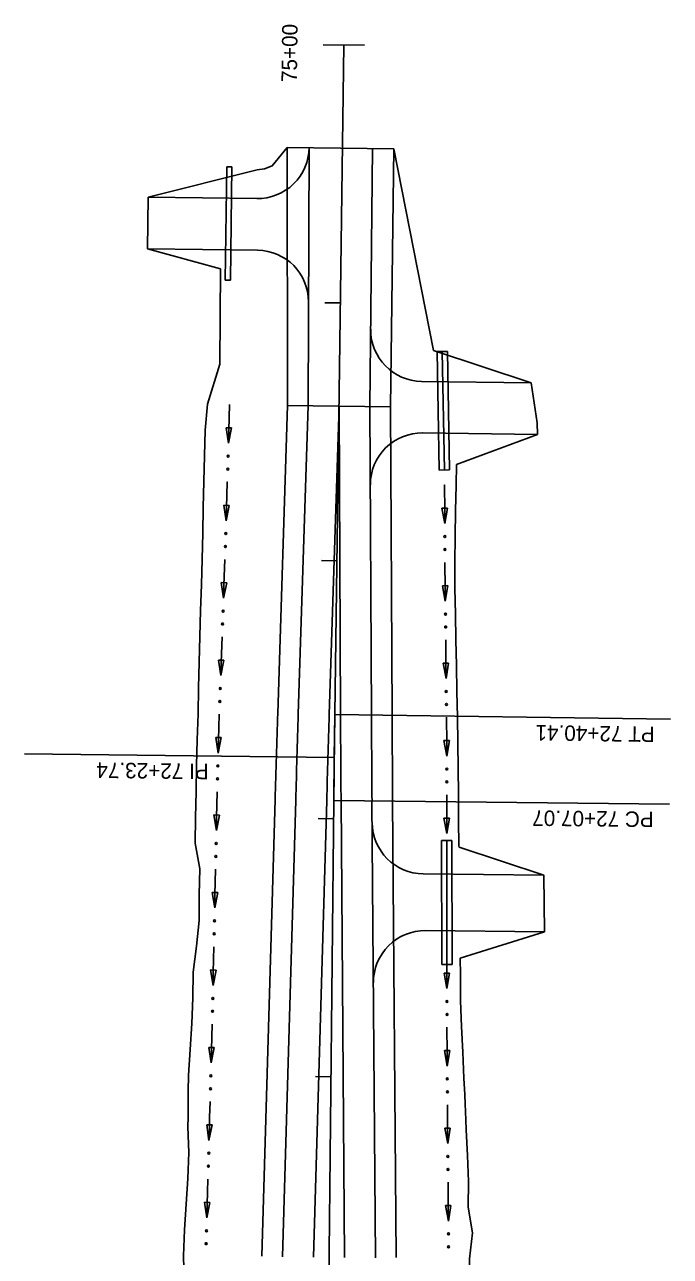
# Model space of a CAD drawing. Extents: x 1611108 to 1749517, y 619561 to 797725.
# Drawn here: x 1728212.3 to 1728462.5, y 773287.1 to 773764.5 of the extents above; entities that cross this region are included whole.
import ezdxf

# ---------------------------------------------------------------- set-up
doc = ezdxf.new("R2010")
doc.units = 0
for name, color, linetype in [('R_Ditch', 7, 'Continuous'), ('R_Drainage', 7, 'Continuous'), ('R_Horz Alg', 7, 'Continuous'), ('R_Horz Alg Annot', 7, 'Continuous'), ('R_Horz Alg Annot_Side Road', 7, 'Continuous'), ('R_Horz Alg Stationing_Side Road', 7, 'Continuous'), ('R_Proposed Const Limits', 7, 'Continuous'), ('R_Proposed Road', 7, 'Continuous'), ('R_Striping', 7, 'Continuous')]:
    doc.layers.add(name, color=color, linetype=linetype)

msp = doc.modelspace()

# ---------------------------------------------------------------- linework, layer by layer
at = {"layer": 'R_Ditch'}
for p, q in [((1728292.54, 773608.22), (1728290.42, 773608.28)), ((1728290.42, 773608.28), (1728291.3, 773602.25)), ((1728291.3, 773602.25), (1728292.54, 773608.22)), ((1728291.62, 773578.2), (1728289.5, 773578.26)), ((1728289.5, 773578.26), (1728290.38, 773572.23)), ((1728290.38, 773572.23), (1728291.62, 773578.2)), ((1728376.17, 773577.1), (1728374.05, 773577.09)), ((1728374.05, 773577.09), (1728375.13, 773571.1)), ((1728375.13, 773571.1), (1728376.17, 773577.1)), ((1728290.65, 773548.17), (1728288.53, 773548.24)), ((1728288.53, 773548.24), (1728289.38, 773542.21)), ((1728289.38, 773542.21), (1728290.65, 773548.17)), ((1728376.34, 773547.07), (1728374.23, 773547.05)), ((1728374.23, 773547.05), (1728375.34, 773541.06)), ((1728375.34, 773541.06), (1728376.34, 773547.07)), ((1728289.57, 773518.15), (1728287.45, 773518.22)), ((1728287.45, 773518.22), (1728288.3, 773512.19)), ((1728288.3, 773512.19), (1728289.57, 773518.15)), ((1728376.63, 773517.03), (1728374.51, 773517.01)), ((1728374.51, 773517.01), (1728375.63, 773511.02)), ((1728375.63, 773511.02), (1728376.63, 773517.03)), ((1728288.48, 773488.14), (1728286.37, 773488.19)), ((1728286.37, 773488.19), (1728287.29, 773482.17)), ((1728287.29, 773482.17), (1728288.48, 773488.14)), ((1728376.93, 773486.99), (1728374.81, 773486.99)), ((1728374.81, 773486.99), (1728375.87, 773480.99)), ((1728375.87, 773480.99), (1728376.93, 773486.99)), ((1728287.81, 773458.11), (1728285.7, 773458.16)), ((1728285.7, 773458.16), (1728286.62, 773452.14)), ((1728286.62, 773452.14), (1728287.81, 773458.11)), ((1728376.94, 773456.95), (1728374.82, 773456.95)), ((1728374.82, 773456.95), (1728375.88, 773450.95)), ((1728375.88, 773450.95), (1728376.94, 773456.95)), ((1728287.16, 773428.08), (1728285.05, 773428.13)), ((1728285.05, 773428.13), (1728285.98, 773422.11)), ((1728285.98, 773422.11), (1728287.16, 773428.08)), ((1728286.52, 773398.05), (1728284.4, 773398.1)), ((1728284.4, 773398.1), (1728285.33, 773392.08)), ((1728285.33, 773392.08), (1728286.52, 773398.05)), ((1728376.99, 773396.87), (1728374.88, 773396.87)), ((1728374.88, 773396.87), (1728375.94, 773390.87)), ((1728375.94, 773390.87), (1728376.99, 773396.87)), ((1728285.81, 773368.02), (1728283.7, 773368.07)), ((1728283.7, 773368.07), (1728284.6, 773362.05)), ((1728284.6, 773362.05), (1728285.81, 773368.02)), ((1728377.08, 773366.84), (1728374.96, 773366.83)), ((1728374.96, 773366.83), (1728376.05, 773360.83)), ((1728376.05, 773360.83), (1728377.08, 773366.84)), ((1728284.99, 773337.99), (1728282.88, 773338.05)), ((1728282.88, 773338.05), (1728283.76, 773332.02)), ((1728283.76, 773332.02), (1728284.99, 773337.99)), ((1728377.28, 773336.81), (1728375.17, 773336.79)), ((1728375.17, 773336.79), (1728376.27, 773330.8)), ((1728376.27, 773330.8), (1728377.28, 773336.81)), ((1728284.14, 773307.96), (1728282.02, 773308.02)), ((1728282.02, 773308.02), (1728282.91, 773302)), ((1728282.91, 773302), (1728284.14, 773307.96)), ((1728377.52, 773306.77), (1728375.4, 773306.75)), ((1728375.4, 773306.75), (1728376.51, 773300.76)), ((1728376.51, 773300.76), (1728377.52, 773306.77))]:
    msp.add_line(p, q, dxfattribs=at)
for points in [[(1728291.75, 773617.25), (1728291.45, 773607.25), (1728291.3, 773602.25)], [(1728290.84, 773587.22), (1728290.53, 773577.26), (1728290.38, 773572.23)], [(1728290.84, 773587.26), (1728290.84, 773587.26), (1728290.84, 773587.22)], [(1728375.07, 773586.13), (1728375.07, 773586.13), (1728375.07, 773586.1)], [(1728375.07, 773586.1), (1728375.11, 773576.13), (1728375.13, 773571.1)], [(1728289.92, 773557.2), (1728289.56, 773547.27), (1728289.38, 773542.21)], [(1728289.92, 773557.24), (1728289.92, 773557.2)], [(1728375.2, 773556.1), (1728375.2, 773556.06)], [(1728375.2, 773556.06), (1728375.29, 773546.12), (1728375.34, 773541.06)], [(1728288.84, 773527.18), (1728288.48, 773517.28), (1728288.3, 773512.19)], [(1728288.84, 773527.22), (1728288.84, 773527.18)], [(1728375.48, 773526.06), (1728375.48, 773526.02)], [(1728375.48, 773526.02), (1728375.58, 773516.12), (1728375.63, 773511.02)], [(1728287.75, 773497.16), (1728287.4, 773487.25), (1728287.29, 773482.17)], [(1728287.76, 773497.2), (1728287.75, 773497.16)], [(1728375.77, 773496.02), (1728375.77, 773495.99)], [(1728375.77, 773495.99), (1728375.87, 773486.15), (1728375.87, 773480.99)], [(1728286.95, 773467.14), (1728286.73, 773457.17), (1728286.62, 773452.14)], [(1728286.95, 773467.17), (1728286.95, 773467.14)], [(1728375.87, 773465.99), (1728375.87, 773465.95)], [(1728375.87, 773465.95), (1728375.88, 773456.23), (1728375.88, 773450.95)], [(1728286.3, 773437.1), (1728286.09, 773427.17), (1728285.98, 773422.11)], [(1728286.3, 773437.14), (1728286.3, 773437.11)], [(1728375.9, 773435.95), (1728375.9, 773435.91)], [(1728375.9, 773435.91), (1728375.91, 773426.23), (1728375.91, 773420.91)], [(1728285.65, 773407.07), (1728285.44, 773397.18), (1728285.33, 773392.08)], [(1728285.65, 773407.11), (1728285.65, 773407.07)], [(1728375.93, 773405.91), (1728375.93, 773405.87)], [(1728375.93, 773400.23), (1728375.94, 773396.23), (1728375.94, 773390.87)], [(1728284.98, 773377.04), (1728284.73, 773367.18), (1728284.6, 773362.05)], [(1728284.99, 773377.08), (1728284.98, 773377.04)], [(1728375.98, 773375.87), (1728375.98, 773375.83)], [(1728375.98, 773375.83), (1728376.02, 773366.23), (1728376.05, 773360.83)], [(1728284.19, 773347.02), (1728284.02, 773340.97), (1728283.91, 773337.19), (1728283.76, 773332.02)], [(1728284.19, 773347.05), (1728284.19, 773347.02)], [(1728376.15, 773345.83), (1728376.15, 773345.8)], [(1728376.15, 773345.8), (1728376.2, 773340.01), (1728376.23, 773336.22), (1728376.27, 773330.8)], [(1728283.34, 773316.99), (1728283.06, 773307.2), (1728282.91, 773302)], [(1728283.34, 773317.03), (1728283.34, 773316.99)], [(1728376.39, 773315.8), (1728376.39, 773315.76)], [(1728376.39, 773315.76), (1728376.46, 773306.22), (1728376.51, 773300.76)]]:
    msp.add_lwpolyline(points, dxfattribs=at)
for centre in [(1728291.18, 773597.25), (1728291.03, 773592.24), (1728290.26, 773567.23), (1728375.19, 773566.09), (1728290.11, 773562.22), (1728375.21, 773561.08), (1728289.23, 773537.21), (1728289.05, 773532.2), (1728375.42, 773536.05), (1728375.47, 773531.04), (1728288.15, 773507.19), (1728375.71, 773506.02), (1728287.97, 773502.18), (1728375.76, 773501.01), (1728287.21, 773477.16), (1728375.9, 773475.98), (1728287.1, 773472.16), (1728375.9, 773470.97), (1728286.55, 773447.13), (1728286.44, 773442.12), (1728285.9, 773417.1), (1728285.8, 773412.09), (1728285.26, 773387.07), (1728375.98, 773385.87), (1728285.14, 773382.06), (1728376, 773380.86), (1728284.51, 773357.04), (1728376.11, 773355.83), (1728284.37, 773352.03), (1728376.15, 773350.82), (1728283.66, 773327.02), (1728283.52, 773322.01), (1728376.35, 773325.79), (1728376.38, 773320.78), (1728282.8, 773296.99), (1728376.58, 773295.75), (1728282.66, 773291.98), (1728376.62, 773290.74)]:
    msp.add_circle(centre, 0.375, dxfattribs=at)
at = {"layer": 'R_Drainage'}
for p, q in [((1728290.09, 773665.47), (1728290.68, 773709.47)), ((1728292.68, 773709.44), (1728290.68, 773709.47)), ((1728292.09, 773665.44), (1728292.68, 773709.44)), ((1728292.09, 773665.44), (1728290.09, 773665.47)), ((1728372.13, 773637.82), (1728376.13, 773637.89)), ((1728372.96, 773591.83), (1728372.13, 773637.82)), ((1728374.96, 773591.86), (1728374.13, 773637.85)), ((1728376.96, 773591.9), (1728376.13, 773637.89)), ((1728372.96, 773591.83), (1728376.96, 773591.9)), ((1728377.9, 773448.24), (1728373.9, 773448.23)), ((1728373.9, 773448.23), (1728373.93, 773400.23)), ((1728375.9, 773448.23), (1728375.93, 773400.23)), ((1728377.9, 773448.24), (1728377.93, 773400.24)), ((1728377.93, 773400.24), (1728373.93, 773400.23))]:
    msp.add_line(p, q, dxfattribs=at)
at = {"layer": 'R_Horz Alg'}
for p, q in [((1728332.55, 773497.1), (1728336.02, 773756.67)), ((1728306.95, 771056.83), (1728332.15, 773463.77))]:
    msp.add_line(p, q, dxfattribs=at)
msp.add_arc((1739790.68, 773343.77), 11459.16, 179.233333, 179.4, dxfattribs=at)
at = {"layer": 'R_Horz Alg Annot'}
msp.add_lwpolyline([(1728332.15, 773463.77), (1728332.33, 773480.43), (1728332.55, 773497.1)], dxfattribs=at)
at = {"layer": 'R_Horz Alg Annot_Side Road'}
for points in [[(1728332.55, 773497.1), (1728462.54, 773495.36)], [(1728332.33, 773480.43), (1728212.34, 773481.86)], [(1728332.15, 773463.77), (1728462.15, 773462.41)]]:
    msp.add_lwpolyline(points, dxfattribs=at)
at = {"layer": 'R_Horz Alg Stationing_Side Road'}
for points in [[(1728328.02, 773756.77), (1728344.02, 773756.56)], [(1728328.69, 773656.76), (1728334.69, 773656.68)], [(1728327.35, 773556.77), (1728333.35, 773556.69)], [(1728326.08, 773456.76), (1728332.08, 773456.69)], [(1728325.03, 773356.76), (1728331.03, 773356.7)]]:
    msp.add_lwpolyline(points, dxfattribs=at)
at = {"layer": 'R_Proposed Const Limits'}
for p, q in [((1728370.75, 773638.19), (1728355.38, 773716.4)), ((1728302.46, 773708.21), (1728260.23, 773697.68)), ((1728288.22, 773669.92), (1728259.96, 773677.68)), ((1728408.56, 773625.69), (1728370.75, 773638.19)), ((1728411.04, 773605.65), (1728379.64, 773594.07)), ((1728380.66, 773445.68), (1728413.51, 773434.84)), ((1728381.13, 773402.68), (1728413.83, 773412.83))]:
    msp.add_line(p, q, dxfattribs=at)
for points in [[(1728302.46, 773708.21), (1728305.34, 773708.65), (1728308.26, 773709.87), (1728314.07, 773716.96)], [(1728283.16, 773617.36), (1728287.98, 773632.89), (1728288.22, 773669.92)], [(1728274.13, 773277.29), (1728273.93, 773287.29), (1728274.33, 773297.29), (1728274.96, 773307.28), (1728275.59, 773317.28), (1728275.93, 773327.27), (1728275.59, 773337.28), (1728275.68, 773341.06), (1728275.66, 773347.28), (1728275.66, 773350.86), (1728275.66, 773350.99), (1728275.86, 773357.28), (1728276.47, 773367.27), (1728277.07, 773377.27), (1728277.51, 773387.26), (1728277.69, 773397.26), (1728278.91, 773407.25), (1728279.98, 773417.24), (1728279.94, 773427.24), (1728280.17, 773437.24), (1728278.46, 773447.25), (1728278.55, 773457.25), (1728278.76, 773467.27), (1728278.97, 773477.31), (1728279.2, 773487.36), (1728279.51, 773497.4), (1728279.76, 773507.4), (1728279.94, 773517.4), (1728280.16, 773527.39), (1728280.52, 773537.39), (1728280.83, 773547.39), (1728281.16, 773557.38), (1728281.33, 773567.38), (1728281.54, 773577.38), (1728281.76, 773587.38), (1728281.97, 773597.38), (1728282.23, 773607.37), (1728283.16, 773617.36)], [(1728380.66, 773445.68), (1728380.61, 773446.18), (1728380.51, 773456.19), (1728380.4, 773466.18), (1728380.31, 773476.14), (1728380.23, 773486.1), (1728380.02, 773496.06), (1728379.82, 773506.06), (1728379.62, 773516.06), (1728379.43, 773526.07), (1728379.24, 773536.07), (1728379.04, 773546.07), (1728379.03, 773556.07), (1728379.2, 773566.07), (1728379.33, 773576.07), (1728379.5, 773586.07), (1728379.64, 773594.07)], [(1728384.36, 773256.95), (1728384.68, 773266.13), (1728384.56, 773276.13), (1728384.67, 773286.13), (1728385.93, 773296.12), (1728384.14, 773306.14), (1728384.34, 773316.14), (1728383.99, 773326.14), (1728383.46, 773336.15), (1728383.3, 773339.94), (1728383.03, 773346.15), (1728382.86, 773349.73), (1728382.85, 773349.86), (1728382.55, 773356.16), (1728382.09, 773366.16), (1728381.58, 773376.17), (1728381.17, 773386.18), (1728381.23, 773396.18), (1728381.13, 773402.68)]]:
    msp.add_lwpolyline(points, dxfattribs=at)
at = {"layer": 'R_Proposed Road'}
for p, q in [((1728314.15, 773616.95), (1728314.07, 773716.96)), ((1728355.38, 773716.4), (1728314.07, 773716.96)), ((1728322.15, 773616.84), (1728322.57, 773716.84)), ((1728346.15, 773616.52), (1728347.08, 773716.52)), ((1728354.15, 773616.41), (1728355.38, 773716.4)), ((1728260.23, 773697.68), (1728259.96, 773677.68)), ((1728302.31, 773697.11), (1728260.23, 773697.68)), ((1728302.59, 773677.11), (1728259.96, 773677.68)), ((1728366.16, 773626.25), (1728408.56, 773625.69)), ((1728310.38, 773497.54), (1728314.15, 773616.95)), ((1728354.15, 773616.41), (1728314.15, 773616.95)), ((1728318.38, 773497.29), (1728322.15, 773616.84)), ((1728346.72, 773496.91), (1728346.15, 773616.52)), ((1728354.72, 773496.95), (1728354.15, 773616.41)), ((1728366.56, 773606.25), (1728411.04, 773605.65)), ((1728309.38, 773464.15), (1728304.3, 773287.12)), ((1728317.37, 773463.92), (1728312.3, 773286.89)), ((1728346.93, 773463.61), (1728348.3, 773286.51)), ((1728354.93, 773463.67), (1728356.3, 773286.58)), ((1728366.79, 773435.33), (1728413.51, 773434.84)), ((1728413.51, 773434.84), (1728413.83, 773412.83)), ((1728367.68, 773413.32), (1728413.83, 773412.83))]:
    msp.add_line(p, q, dxfattribs=at)
msp.add_lwpolyline([(1728408.56, 773625.69), (1728410.97, 773610.22), (1728411.04, 773605.65)], dxfattribs=at)
for centre, radius, start, end in [((1728302.57, 773717.11), 20, 269.2333, 359.2333), ((1728302.32, 773657.11), 20, 359.7583, 89.2333), ((1728366.43, 773646.25), 20, 179.4659, 269.2333), ((1728366.3, 773586.25), 20, 89.2333, 180.275), ((1739788.2, 773135.42), 11483.53, 178.192954, 178.35962), ((1739788.2, 773135.42), 11475.53, 178.192954, 178.35962), ((1739793.17, 773552.12), 11446.58, 180.276344, 180.443011), ((1739793.17, 773552.12), 11438.58, 180.276344, 180.443011), ((1728367, 773455.33), 20, 180.4416, 269.4), ((1728367.47, 773393.32), 20, 89.4, 180.4416)]:
    msp.add_arc(centre, radius, start, end, dxfattribs=at)
at = {"layer": 'R_Striping'}
for p, q in [((1728334.15, 773616.68), (1728330.38, 773497.13)), ((1728334.15, 773616.68), (1728334.72, 773497.07)), ((1728329.37, 773463.8), (1728324.3, 773286.77)), ((1728334.93, 773463.74), (1728336.3, 773286.64))]:
    msp.add_line(p, q, dxfattribs=at)
for centre, radius, start, end in [((1739788.2, 773135.42), 11463.53, 178.191865, 178.358531), ((1739793.17, 773552.12), 11458.57, 180.275252, 180.441919)]:
    msp.add_arc(centre, radius, start, end, dxfattribs=at)

# ---------------------------------------------------------------- texts
at = {"layer": 'R_Horz Alg Annot_Side Road'}
for s, rotation, p in [('PT 72+40.41', 179.2333, (1728456.5, 773492.44)), ('PI 72+23.74', 179.3167, (1728283.67, 773478.01)), ('PC 72+07.07', 179.4, (1728456.11, 773459.47))]:
    msp.add_text(s, height=6, rotation=rotation, dxfattribs=at).set_placement(p)
at = {"layer": 'R_Horz Alg Stationing_Side Road'}
msp.add_text('75+00', height=6, rotation=89.2333, dxfattribs=at).set_placement((1728317.83, 773742.26))

doc.saveas('drawing.dxf')
